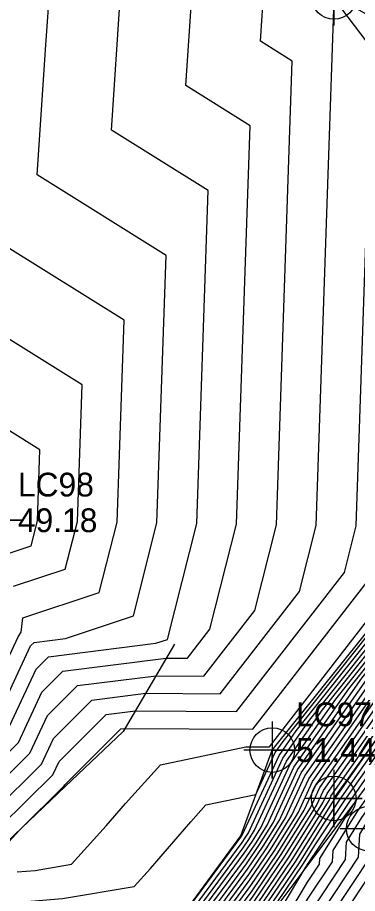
# Model space of a CAD drawing. Extents: x 2188792 to 2191981, y 386090 to 389710.
# Drawn here: x 2189959 to 2189994.7, y 387443.1 to 387535.2 of the extents above; entities that cross this region are included whole.
import ezdxf

# ---------------------------------------------------------------- set-up
doc = ezdxf.new("R2010")
doc.units = 0
for name, color, linetype in [('DTM Contours Major', 7, 'Continuous'), ('DTM Contours Minor', 7, 'Continuous'), ('Exist DTM Breakline', 7, 'Continuous'), ('Exist DTM Breakline Cogo Elevation', 7, 'Continuous'), ('Exist DTM Breakline Cogo Number', 7, 'Continuous'), ('Exist DTM Breakline Cogo Point CELL', 7, 'Continuous'), ('Exist DTM QL2 LIDAR Elevation Point', 7, 'Continuous'), ('Exist DTM Regular Point Underwater CELL', 7, 'Continuous'), ('Exist DTM Regular Point Underwater Cogo Elevation', 7, 'Continuous'), ('Exist DTM Regular Point Underwater Cogo Number', 7, 'Continuous'), ('PH Exist DTM Breakline', 7, 'Continuous')]:
    doc.layers.add(name, color=color, linetype=linetype)

msp = doc.modelspace()

# ---------------------------------------------------------------- linework, layer by layer
at = {"layer": 'DTM Contours Major'}
for points in [[(2189956.665, 387461.26), (2189960.354, 387469.136), (2189960.736, 387469.517), (2189964.05, 387469.936), (2189971.173, 387472.29), (2189973.658, 387482.085), (2189974.62, 387510.207), (2189961.043, 387518.678), (2189961.921, 387531.826), (2189962.671, 387542.238), (2189947.626, 387551.564)], [(2189984.352, 387440.029), (2189988.632, 387446.331), (2189991.161, 387450.388), (2189992.862, 387452.939), (2190007.704, 387474.081), (2190010.026, 387477.237), (2190010.866, 387478.407), (2190020.031, 387491.642), (2190026.918, 387501.402), (2190027.261, 387501.831), (2190027.928, 387502.771), (2190027.942, 387502.789), (2190045.269, 387526.683), (2190045.546, 387527.079), (2190062.971, 387551.105)], [(2189957.921, 387412.608), (2189960.495, 387415.615), (2189963.565, 387419.576), (2189966.033, 387422.473), (2189971.823, 387427.618), (2189973.953, 387429.864), (2189975.86, 387430.935), (2189976.679, 387433.44), (2189978.768, 387435.688), (2189981.855, 387440.257), (2189983.77, 387442.845), (2189986.732, 387447.206), (2189989.796, 387452.121), (2189990.78, 387454.257), (2190003.512, 387472.407), (2190008.404, 387478.538), (2190020.573, 387495.783), (2190026.132, 387502.74), (2190026.608, 387503.41), (2190026.821, 387503.676), (2190039.173, 387520.711), (2190044.314, 387528.031), (2190057.303, 387545.941)], [(2189957.493, 387397.732), (2189959.964, 387401.028), (2189969.853, 387414.121), (2189972.085, 387417.1), (2189976.117, 387420.341), (2189977.065, 387420.694), (2189985.076, 387432.063), (2189985.095, 387433.258), (2189987.112, 387436.647), (2189989.644, 387440.904), (2189993.471, 387446.692), (2189993.574, 387448.499), (2189995.205, 387451.102), (2190002.478, 387461.302), (2190012.599, 387475.058), (2190022.556, 387488.916), (2190029.949, 387499.592), (2190030.371, 387500.182), (2190030.688, 387500.641), (2190041.096, 387515.254), (2190048.167, 387524.986), (2190060.341, 387542.129)], [(2189955.068, 387412.785), (2189960.286, 387418.879), (2189961.085, 387419.91), (2189965.998, 387425.677), (2189967.889, 387427.358), (2189972.645, 387432.374), (2189973.523, 387432.867), (2189973.901, 387434.022), (2189978.006, 387438.439), (2189979.705, 387440.954), (2189983.189, 387445.661), (2189984.832, 387448.081), (2189986.532, 387450.808), (2189988.83, 387455.794), (2189996.597, 387466.866), (2190006.879, 387479.75), (2190014.228, 387490.164), (2190025.003, 387503.648), (2190025.288, 387504.048), (2190025.699, 387504.563), (2190033.078, 387514.739), (2190043.082, 387528.982), (2190051.636, 387540.776)], [(2189957.168, 387450.113), (2189962.705, 387455.58), (2189963.359, 387456.976), (2189968.321, 387461.932), (2189971.382, 387462.319), (2189982.029, 387462.255), (2189993.359, 387476.866), (2189994.6, 387481.754), (2189995.932, 387520.719), (2190013.29, 387497.82), (2190021.199, 387507.858), (2190021.483, 387508.219), (2190037.161, 387527.264), (2190028.053, 387532.529), (2190026.213, 387539.316)], [(2189953.618, 387431.202), (2189959.565, 387434.157), (2189961.984, 387436.074), (2189969.442, 387436.668), (2189973.707, 387437.385), (2189977.243, 387441.19), (2189977.555, 387441.65), (2189982.607, 387448.477), (2189982.933, 387448.956), (2189983.269, 387449.495), (2189986.88, 387457.33), (2189989.682, 387461.324), (2190005.354, 387480.961), (2190007.883, 387484.545), (2190023.875, 387504.556), (2190023.967, 387504.687), (2190024.577, 387505.45), (2190026.983, 387508.767), (2190041.85, 387529.933), (2190045.968, 387535.612)]]:
    msp.add_lwpolyline(points, dxfattribs=at)
at = {"layer": 'DTM Contours Minor'}
for points in [[(2189954.903, 387454.862), (2189959.081, 387458.988), (2189961.556, 387464.272), (2189963.77, 387466.483), (2189974.639, 387467.856), (2189976.863, 387467.842), (2189979.229, 387470.893), (2189982.035, 387481.952), (2189983.467, 387523.828), (2189976.698, 387528.051), (2189978.02, 387547.851), (2189978.106, 387549.034), (2189958.031, 387561.478)], [(2189957.873, 387460.124), (2189960.955, 387466.704), (2189962.253, 387468), (2189973.526, 387469.424), (2189974.754, 387469.829), (2189977.847, 387482.019), (2189979.043, 387517.017), (2189968.871, 387523.365), (2189969.971, 387539.838), (2189970.388, 387545.636), (2189952.829, 387556.521)], [(2189958.048, 387448.514), (2189959.221, 387449.811), (2189963.913, 387454.444), (2189963.96, 387454.544), (2189969.838, 387460.415), (2189970.296, 387460.473), (2189983.751, 387460.392), (2189998.07, 387478.857), (2189998.788, 387481.688), (2189999.56, 387504.257), (2190009.614, 387490.994), (2190022.026, 387506.747), (2190022.471, 387507.313), (2190035.891, 387523.615), (2190040.864, 387530.695), (2190041.434, 387531.48), (2190058.134, 387555.179)], [(2189958.943, 387445.392), (2189960.837, 387445.543), (2189964.656, 387446.184), (2189968.309, 387450.223), (2189970.339, 387452.577), (2189974.036, 387456.657), (2189982.989, 387458.545), (2189985.473, 387458.53), (2190002.78, 387480.847), (2190002.977, 387481.622), (2190003.188, 387487.795), (2190005.938, 387484.167), (2190022.852, 387505.635), (2190023.46, 387506.407), (2190028.397, 387512.404), (2190041.111, 387530.504), (2190042.568, 387532.513), (2190058.398, 387554.979)], [(2189955.119, 387438.452), (2189959.956, 387442.286), (2189963.705, 387442.584), (2189971.264, 387443.854), (2189972.973, 387445.744), (2189977.203, 387450.649), (2189978.807, 387452.419), (2189984.064, 387453.528), (2189986.1, 387457.945), (2189986.916, 387459.108), (2190004.744, 387481.446), (2190005.345, 387482.298), (2190023.423, 387504.92), (2190023.439, 387504.943), (2190024.129, 387505.805), (2190024.545, 387506.379), (2190041.357, 387530.314), (2190043.701, 387533.546), (2190058.663, 387554.778)], [(2189957.342, 387436.305), (2189960.97, 387439.18), (2189966.574, 387439.626), (2189976.709, 387441.329), (2189977.091, 387441.74), (2189977.125, 387441.79), (2189982.491, 387449.04), (2189982.553, 387449.13), (2189982.616, 387449.233), (2189986.49, 387457.637), (2189988.299, 387460.216), (2190005.049, 387481.204), (2190006.614, 387483.421), (2190023.649, 387504.738), (2190023.703, 387504.815), (2190024.353, 387505.628), (2190025.764, 387507.573), (2190041.603, 387530.124), (2190044.835, 387534.579), (2190058.927, 387554.577)], [(2189955.863, 387403.686), (2189960.537, 387409.923), (2189962.716, 387412.808), (2189967.226, 387418.828), (2189975.374, 387425.378), (2189977.291, 387426.092), (2189980.462, 387430.593), (2189980.5, 387432.909), (2189983.924, 387438.665), (2189984.435, 387439.422), (2189984.468, 387439.466), (2189989.012, 387446.156), (2189990.295, 387448.214), (2189993.358, 387452.805), (2190003.177, 387466.793), (2190010.541, 387476.802), (2190013.204, 387480.508), (2190027.711, 387501.458), (2190027.772, 387501.543), (2190028.391, 387502.438), (2190029.827, 387504.455), (2190046.003, 387526.716), (2190047.848, 387529.313), (2190063.603, 387551)], [(2189956.27, 387402.198), (2189960.394, 387407.699), (2189964.5, 387413.136), (2189968.441, 387418.396), (2189975.56, 387424.119), (2189977.234, 387424.742), (2189981.616, 387430.96), (2189981.649, 387432.997), (2189985.085, 387438.773), (2189989.245, 387445.764), (2189989.392, 387445.981), (2189989.429, 387446.041), (2189993.853, 387452.672), (2189998.65, 387459.506), (2190011.055, 387476.366), (2190015.542, 387482.61), (2190028.271, 387500.992), (2190028.421, 387501.203), (2190028.965, 387501.988), (2190032.644, 387507.154), (2190046.544, 387526.283), (2190050.971, 387532.517), (2190064.1, 387550.59)], [(2189984.235, 387440.592), (2189988.252, 387446.506), (2189992.027, 387452.562), (2189992.367, 387453.072), (2189997.801, 387460.812), (2190009.043, 387476.841), (2190009.625, 387477.569), (2190025.649, 387500.279), (2190027.035, 387502.013), (2190027.664, 387502.899), (2190027.718, 387502.967), (2190044.05, 387525.489), (2190045.3, 387527.269), (2190061.837, 387550.072)], [(2189955.19, 387406.762), (2189959.632, 387412.503), (2189960.621, 387413.657), (2189965.053, 387419.376), (2189966.055, 387420.551), (2189974.184, 387427.774), (2189974.737, 387428.358), (2189977.262, 387429.776), (2189978.346, 387433.091), (2189979.225, 387434.037), (2189983.145, 387439.839), (2189984.119, 387441.155), (2189987.872, 387446.681), (2189991.754, 387452.908), (2189991.95, 387453.335), (2190007.66, 387475.732), (2190009.32, 387477.811), (2190024.38, 387499.155), (2190026.81, 387502.195), (2190027.4, 387503.027), (2190027.494, 387503.144), (2190042.83, 387524.295), (2190045.054, 387527.46), (2190060.704, 387549.039)], [(2190066.588, 387548.537), (2190049.25, 387524.121), (2190046.73, 387520.654), (2190031.837, 387499.742), (2190031.67, 387499.501), (2190031.068, 387498.659), (2190027.232, 387493.119), (2190013.629, 387474.186), (2190010.451, 387469.867), (2190000.703, 387456.196), (2189998.289, 387452.392), (2189996.348, 387449.596), (2189996.21, 387447.174), (2189989.807, 387437.489), (2189988.463, 387435.23), (2189987.393, 387433.432), (2189987.383, 387432.798), (2189976.952, 387417.995), (2189976.488, 387417.822), (2189974.514, 387416.236), (2189973.422, 387414.778), (2189959.678, 387396.581), (2189958.309, 387394.755)], [(2189955.108, 387407.428), (2189959.062, 387412.538), (2189960.579, 387414.31), (2189964.557, 387419.443), (2189966.047, 387421.192), (2189973.397, 387427.722), (2189974.476, 387428.86), (2189976.795, 387430.162), (2189977.791, 387433.208), (2189979.072, 387434.587), (2189982.715, 387439.979), (2189984.003, 387441.719), (2189987.492, 387446.856), (2189991.101, 387452.646), (2189991.56, 387453.643), (2190006.277, 387474.624), (2190009.014, 387478.054), (2190023.111, 387498.031), (2190026.584, 387502.376), (2190027.136, 387503.154), (2190027.269, 387503.321), (2190041.611, 387523.1), (2190044.807, 387527.65), (2190059.57, 387548.006)], [(2190067.418, 387547.671), (2190051.466, 387526.048), (2190049.791, 387523.688), (2190049.547, 387523.353), (2190032.412, 387499.293), (2190032.32, 387499.161), (2190031.628, 387498.193), (2190029.57, 387495.221), (2190015.34, 387475.415), (2190014.879, 387474.621), (2190014.239, 387473.68), (2190005.531, 387459.96), (2189997.647, 387448.599), (2189997.579, 387447.415), (2189989.888, 387435.781), (2189989.138, 387434.522), (2189988.542, 387433.519), (2189988.536, 387433.165), (2189976.896, 387416.646), (2189976.674, 387416.563), (2189975.729, 387415.804), (2189975.206, 387415.106), (2189959.534, 387394.357), (2189958.717, 387393.266)], [(2189958.491, 387412.573), (2189960.537, 387414.962), (2189964.061, 387419.509), (2189966.04, 387421.833), (2189972.61, 387427.67), (2189974.214, 387429.362), (2189976.327, 387430.549), (2189977.235, 387433.324), (2189978.92, 387435.137), (2189982.285, 387440.118), (2189983.887, 387442.282), (2189987.112, 387447.031), (2189990.448, 387452.383), (2189991.17, 387453.95), (2190004.894, 387473.516), (2190008.709, 387478.296), (2190021.842, 387496.907), (2190026.358, 387502.558), (2190026.872, 387503.282), (2190027.045, 387503.499), (2190040.392, 387521.906), (2190044.561, 387527.84), (2190058.437, 387546.974)], [(2189957.35, 387412.644), (2189960.453, 387416.268), (2189963.069, 387419.643), (2189966.026, 387423.114), (2189971.037, 387427.566), (2189973.691, 387430.366), (2189975.393, 387431.321), (2189976.124, 387433.557), (2189978.615, 387436.238), (2189981.425, 387440.397), (2189983.654, 387443.408), (2189986.352, 387447.381), (2189989.143, 387451.858), (2189990.39, 387454.565), (2190002.129, 387471.299), (2190008.099, 387478.781), (2190019.304, 387494.66), (2190025.906, 387502.921), (2190026.344, 387503.538), (2190026.596, 387503.854), (2190037.954, 387519.517), (2190044.068, 387528.221), (2190056.17, 387544.908)], [(2189957.901, 387396.243), (2189959.821, 387398.805), (2189971.637, 387414.449), (2189973.299, 387416.668), (2189976.302, 387419.082), (2189977.009, 387419.345), (2189986.229, 387432.43), (2189986.244, 387433.345), (2189987.787, 387435.939), (2189989.725, 387439.197), (2189994.84, 387446.933), (2189994.978, 387449.349), (2189995.635, 387450.396), (2190006.465, 387465.585), (2190013.114, 387474.622), (2190024.894, 387491.018), (2190030.509, 387499.126), (2190031.021, 387499.841), (2190031.263, 387500.191), (2190043.913, 387517.954), (2190048.709, 387524.553), (2190063.465, 387545.333)], [(2189955.658, 387453.279), (2189960.289, 387457.852), (2189962.157, 387461.84), (2189965.287, 387464.966), (2189973.554, 387466.01), (2189978.585, 387465.98), (2189983.939, 387472.884), (2189986.223, 387481.886), (2189987.89, 387530.638), (2189984.526, 387532.738), (2189985.313, 387544.525)], [(2189956.78, 387412.679), (2189960.412, 387416.92), (2189962.573, 387419.71), (2189966.019, 387423.755), (2189970.25, 387427.514), (2189973.429, 387430.868), (2189974.925, 387431.708), (2189975.568, 387433.673), (2189978.463, 387436.788), (2189980.995, 387440.536), (2189983.538, 387443.971), (2189985.972, 387447.556), (2189988.49, 387451.595), (2189990, 387454.872), (2190000.746, 387470.191), (2190007.794, 387479.023), (2190018.035, 387493.536), (2190025.681, 387503.103), (2190026.08, 387503.665), (2190026.372, 387504.031), (2190036.735, 387518.323), (2190043.821, 387528.411), (2190055.036, 387543.875)], [(2189956.209, 387412.714), (2189960.37, 387417.573), (2189962.077, 387419.776), (2189966.012, 387424.396), (2189969.463, 387427.462), (2189973.168, 387431.37), (2189974.458, 387432.094), (2189975.012, 387433.789), (2189978.31, 387437.338), (2189980.565, 387440.675), (2189983.421, 387444.534), (2189985.592, 387447.731), (2189987.838, 387451.333), (2189989.61, 387455.179), (2189999.363, 387469.082), (2190007.489, 387479.265), (2190016.766, 387492.412), (2190025.455, 387503.285), (2190025.816, 387503.793), (2190026.148, 387504.208), (2190035.516, 387517.128), (2190043.575, 387528.601), (2190053.903, 387542.842)], [(2189955.639, 387412.749), (2189960.328, 387418.226), (2189961.581, 387419.843), (2189966.005, 387425.036), (2189968.676, 387427.41), (2189972.906, 387431.872), (2189973.991, 387432.481), (2189974.457, 387433.906), (2189978.158, 387437.888), (2189980.135, 387440.815), (2189983.305, 387445.098), (2189985.212, 387447.906), (2189987.185, 387451.07), (2189989.22, 387455.486), (2189997.98, 387467.974), (2190007.184, 387479.507), (2190015.497, 387491.288), (2190025.229, 387503.466), (2190025.552, 387503.921), (2190025.923, 387504.386), (2190034.297, 387515.934), (2190043.329, 387528.792), (2190052.769, 387541.809)], [(2189954.498, 387412.82), (2189960.244, 387419.531), (2189960.589, 387419.977), (2189965.991, 387426.318), (2189967.102, 387427.306), (2189972.383, 387432.876), (2189973.056, 387433.254), (2189973.345, 387434.138), (2189977.853, 387438.989), (2189979.275, 387441.093), (2189983.073, 387446.224), (2189984.452, 387448.256), (2189985.88, 387450.545), (2189988.44, 387456.101), (2189995.214, 387465.757), (2190006.574, 387479.992), (2190012.959, 387489.04), (2190024.778, 387503.83), (2190025.024, 387504.176), (2190025.475, 387504.741), (2190031.859, 387513.545), (2190042.836, 387529.172), (2190050.502, 387539.743)], [(2189954.865, 387418.975), (2189959.208, 387421.109), (2189960.948, 387421.931), (2189962.292, 387422.624), (2189965.984, 387426.959), (2189966.316, 387427.254), (2189972.121, 387433.378), (2189972.589, 387433.64), (2189972.79, 387434.255), (2189977.701, 387439.539), (2189978.845, 387441.233), (2189982.956, 387446.787), (2189984.072, 387448.431), (2189985.227, 387450.283), (2189988.05, 387456.408), (2189993.831, 387464.649), (2190006.269, 387480.234), (2190011.69, 387487.917), (2190024.552, 387504.011), (2190024.76, 387504.304), (2190025.25, 387504.918), (2190030.64, 387512.351), (2190042.589, 387529.363), (2190049.369, 387538.711)], [(2189957.086, 387399.221), (2189960.107, 387403.252), (2189968.069, 387413.793), (2189970.87, 387417.532), (2189975.931, 387421.6), (2189977.121, 387422.044), (2189983.922, 387431.695), (2189983.946, 387433.171), (2189986.436, 387437.356), (2189989.563, 387442.612), (2189992.101, 387446.451), (2189992.17, 387447.65), (2189994.776, 387451.808), (2189998.492, 387457.02), (2190012.085, 387475.494), (2190020.218, 387486.814), (2190029.39, 387500.059), (2190029.721, 387500.522), (2190030.114, 387501.09), (2190038.279, 387512.554), (2190047.626, 387525.418), (2190057.218, 387538.925)], [(2189955.245, 387425.507), (2189964.012, 387429.863), (2189967.704, 387429.496), (2189971.86, 387433.88), (2189972.122, 387434.027), (2189972.234, 387434.371), (2189977.548, 387440.089), (2189978.415, 387441.372), (2189982.84, 387447.35), (2189983.693, 387448.606), (2189984.574, 387450.02), (2189987.66, 387456.716), (2189992.448, 387463.541), (2190005.964, 387480.477), (2190010.421, 387486.793), (2190024.326, 387504.193), (2190024.496, 387504.432), (2190025.026, 387505.096), (2190029.421, 387511.156), (2190042.343, 387529.553), (2190048.235, 387537.678)], [(2189954.431, 387428.355), (2189961.788, 387432.01), (2189962.998, 387432.969), (2189969.913, 387433.519), (2189970.706, 387433.44), (2189971.598, 387434.382), (2189971.654, 387434.413), (2189971.678, 387434.487), (2189977.396, 387440.64), (2189977.985, 387441.511), (2189982.724, 387447.913), (2189983.313, 387448.781), (2189983.922, 387449.758), (2189987.27, 387457.023), (2189991.065, 387462.433), (2190005.659, 387480.719), (2190009.152, 387485.669), (2190024.1, 387504.375), (2190024.231, 387504.559), (2190024.802, 387505.273), (2190028.202, 387509.962), (2190042.096, 387529.743), (2190047.102, 387536.645)], [(2189956.413, 387451.696), (2189961.497, 387456.716), (2189962.758, 387459.408), (2189966.804, 387463.449), (2189972.468, 387464.164), (2189980.307, 387464.117), (2189988.649, 387474.875), (2189990.412, 387481.82), (2189992.305, 387537.181), (2190016.966, 387504.647), (2190020.372, 387508.97), (2190020.495, 387509.125), (2190027.247, 387517.328), (2189992.67, 387537.316)], [(2189956.678, 387400.709), (2189960.251, 387405.476), (2189966.285, 387413.464), (2189969.655, 387417.964), (2189975.746, 387422.859), (2189977.178, 387423.393), (2189982.769, 387431.328), (2189982.798, 387433.084), (2189985.761, 387438.064), (2189989.482, 387444.319), (2189990.732, 387446.21), (2189990.766, 387446.8), (2189994.346, 387452.513), (2189994.505, 387452.737), (2190011.57, 387475.93), (2190017.88, 387484.712), (2190028.83, 387500.525), (2190029.071, 387500.862), (2190029.54, 387501.539), (2190035.462, 387509.854), (2190047.085, 387525.851), (2190054.095, 387535.721)], [(2189955.457, 387462.396), (2189959.061, 387470.091), (2189959.369, 387470.581), (2189959.536, 387472.088), (2189967.592, 387474.752), (2189969.47, 387482.151), (2189970.196, 387503.396), (2189953.216, 387513.992)], [(2189958.563, 387475.411), (2189964.012, 387477.213), (2189965.282, 387482.217), (2189965.773, 387496.586), (2189945.388, 387509.305)], [(2189957.59, 387478.735), (2189960.431, 387479.674), (2189961.093, 387482.283), (2189961.349, 387489.775), (2189937.561, 387504.619)]]:
    msp.add_lwpolyline(points, dxfattribs=at)
at = {"layer": 'Exist DTM Breakline'}
for points in [[(2189985.78, 387458.197), (2190024.035, 387505.879), (2190058.15, 387556.911), (2190090.329, 387601.585), (2190123.453, 387645.538), (2190155.634, 387692.318), (2190180.541, 387728.105)], [(2189992.243, 387453.105), (2190028.023, 387502.725), (2190063.31, 387551.461), (2190096.85, 387598.566), (2190127.537, 387642.384), (2190160.72, 387688.44), (2190186.991, 387724.396)]]:
    msp.add_lwpolyline(points, dxfattribs=at)
at = {"layer": 'Exist DTM Breakline Cogo Point CELL'}
for points in [[(2189985.78, 387461.197), (2189985.78, 387455.197), (2189985.78, 387458.197), (2189988.78, 387458.197), (2189982.78, 387458.197)], [(2189992.243, 387456.105), (2189992.243, 387450.105), (2189992.243, 387453.105), (2189995.243, 387453.105), (2189989.243, 387453.105)], [(2189995.924, 387452.921), (2189995.924, 387446.921), (2189995.924, 387449.921), (2189998.924, 387449.921), (2189992.924, 387449.921)]]:
    msp.add_lwpolyline(points, dxfattribs=at)
for centre in [(2189985.78, 387458.197), (2189992.243, 387453.105), (2189995.924, 387449.921)]:
    msp.add_circle(centre, 2.344, dxfattribs=at)
at = {"layer": 'Exist DTM QL2 LIDAR Elevation Point'}
msp.add_line((2189960.104, 387470.149), (2189960.104, 387470.149), dxfattribs=at)
at = {"layer": 'Exist DTM Regular Point Underwater CELL'}
for points in [[(2189992.263, 387540.371), (2189992.263, 387534.371), (2189992.263, 387537.371), (2189995.263, 387537.371), (2189989.263, 387537.371)], [(2189956.53, 387485.355), (2189956.53, 387479.355), (2189956.53, 387482.355), (2189959.53, 387482.355), (2189953.53, 387482.355)]]:
    msp.add_lwpolyline(points, dxfattribs=at)
msp.add_circle((2189992.263, 387537.371), 2.344, dxfattribs=at)
at = {"layer": 'PH Exist DTM Breakline'}
for points in [[(2189975.499, 387469.317), (2189970.105, 387460.148), (2189964.006, 387454.356), (2189957.907, 387448.563), (2189950.186, 387443.216), (2189943.14, 387440.61), (2189939.074, 387439.65), (2189930.083, 387439.298), (2189922.54, 387441.448), (2189916.319, 387445.798), (2189910.099, 387450.147)], [(2189887.345, 387318.68), (2189892.587, 387326.516), (2189897.829, 387334.352), (2189903.071, 387342.188), (2189908.394, 387348.992), (2189913.717, 387355.796), (2189919.04, 387362.601), (2189924.363, 387369.405), (2189929.58, 387376.911), (2189936.401, 387386.159), (2189940.535, 387392.152), (2189944.67, 387398.146), (2189949.557, 387405.484), (2189954.444, 387412.823), (2189960.212, 387420.027), (2189965.981, 387427.231), (2189971.527, 387434.519), (2189977.073, 387441.807), (2189982.464, 387449.171), (2189985.78, 387458.197)], [(2189994.327, 387452.545), (2189989.403, 387445.976), (2189984.48, 387439.407), (2189979.557, 387432.838), (2189977.439, 387429.629), (2189975.013, 387427.829), (2189966.069, 387419.239), (2189960.699, 387412.437), (2189955.329, 387405.634), (2189950.593, 387398.64), (2189945.856, 387391.646), (2189941.119, 387384.652), (2189935.964, 387377.579), (2189930.809, 387370.505), (2189925.654, 387363.432), (2189920.499, 387356.359), (2189915.384, 387348.649), (2189910.269, 387340.94), (2189905.154, 387333.231), (2189900.038, 387325.521), (2189894.923, 387317.812)]]:
    msp.add_lwpolyline(points, dxfattribs=at)

# ---------------------------------------------------------------- texts
at = {"layer": 'Exist DTM Breakline Cogo Elevation'}
msp.add_text('51.44', height=2.5, dxfattribs=at).set_placement((2189988.28, 387456.947))
at = {"layer": 'Exist DTM Breakline Cogo Number'}
msp.add_text('LC97', height=2.5, dxfattribs=at).set_placement((2189988.28, 387460.697))
at = {"layer": 'Exist DTM Regular Point Underwater Cogo Elevation'}
msp.add_text('49.18', height=2.5, dxfattribs=at).set_placement((2189959.03, 387481.105))
at = {"layer": 'Exist DTM Regular Point Underwater Cogo Number'}
msp.add_text('LC98', height=2.5, dxfattribs=at).set_placement((2189959.03, 387484.855))

doc.saveas('drawing.dxf')
